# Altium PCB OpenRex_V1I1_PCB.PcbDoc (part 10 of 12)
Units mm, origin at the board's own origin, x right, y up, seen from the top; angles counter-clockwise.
Board outline 70 x 95 mm, 10 copper layers (L1, L2, L3, L4 (PWR), L5 (PWR), L6 (PWR), L7 (PWR), L8, L9, L10), stack 1.632 mm thick; 1080 components, 708 nets, 3831 pads, 2373 vias.
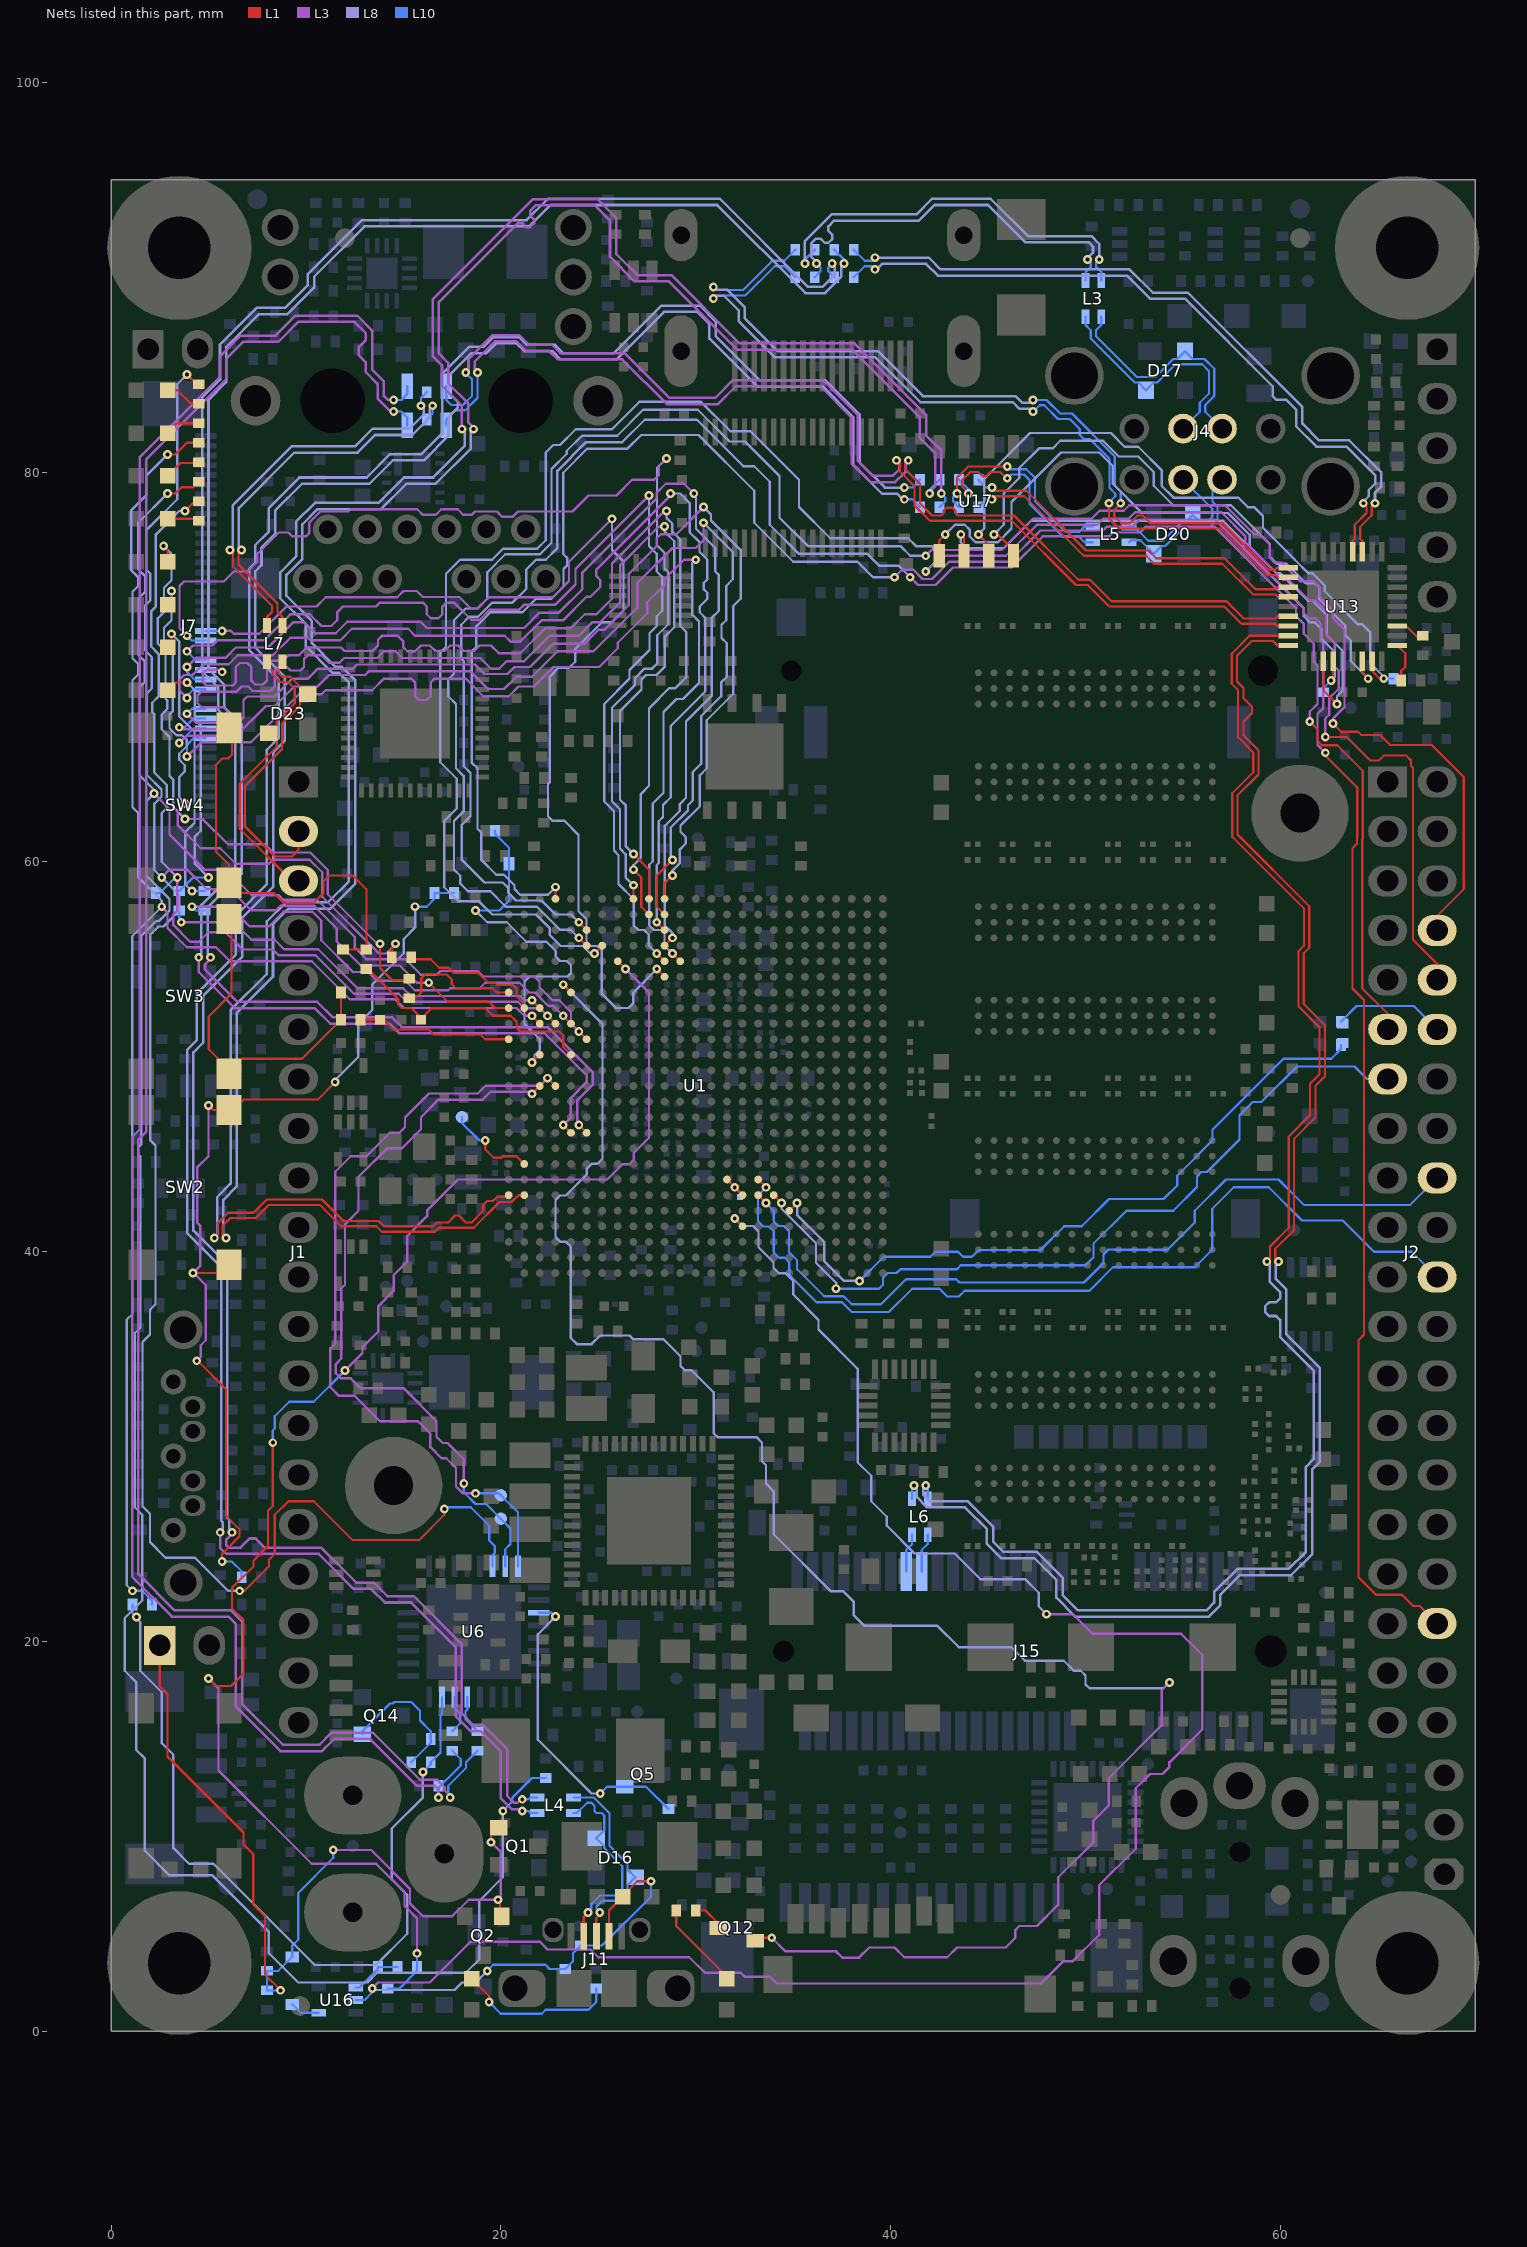
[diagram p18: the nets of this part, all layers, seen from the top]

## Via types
v1: diameter 0.45, hole 0.2, L1 to L10, tented both sides, 2369 vias
v2: diameter 1, hole 0.5, L1 to L10, tented top, 4 vias

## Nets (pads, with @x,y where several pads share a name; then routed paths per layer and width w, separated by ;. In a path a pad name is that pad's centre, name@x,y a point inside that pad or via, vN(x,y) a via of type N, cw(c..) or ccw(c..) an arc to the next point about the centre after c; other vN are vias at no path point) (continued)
UART2_RXD: TP30.1 U1.D13 U6.32 | length 40.9
  L1 w0.114: v1(22.4,48.9) U1.D13@22.8,48.5
  L3 w0.12: v1(18.7,27.6) 18.056,27.6 17.702,27.954 17.702,28.898 17.2,29.4 16.956,29.4 16.385,29.971 16.385,30.659 15.744,31.3 13.8,31.3 12.5,32.6 11.7,32.6 11.255,33.045 11.255,35.047 11.5,35.292 11.5,44.1 12.3,44.9 13.1,44.9 14.3,46.1 14.8,46.1 15.085,46.385 15.085,46.885 16.315,48.115 18.815,48.115 19.215,48.515 22.015,48.515 v1(22.4,48.9)
  L10 w0.114: v1(18.7,27.6) 19.9,27.6 TP30.1@20,27.5 20.875,26.625 U6.32@20.875,23.85
UART2_TXD: TP29.1 U1.C13 U6.31 | length 38
  L1 w0.114: v1(21.6,48.1) U1.C13@22,48.5
  L3 w0.12: v1(18.1,28.1) 18.1,29.344 17.259,30.185 17.015,30.185 16.7,30.5 16.7,31.3 15,33 12.8,33 12.3,33.5 11.8,33.5 11.535,33.765 11.535,34.235 11.815,34.515 11.815,38.115 12,38.3 12,41.4 12.7,42.1 12.7,43.844 14.156,45.3 14.914,45.3 15.9,46.286 15.9,46.9 16.8,47.8 19.068,47.8 19.47,48.202 21.498,48.202 v1(21.6,48.1)
  L10 w0.114: v1(18.1,28.1) 18.1,27.656 18.7,27.056 19.244,27.056 TP29.1@20,26.3 20.5,25.8 20.5,25 20.225,24.725 U6.31@20.225,23.85
UART3_CTS: J2.36 U1.D25 | length 132.1
  L1 w0.114: U1.D25@22.8,58.1 v1(22.8,58.7) ; v1(62.3,65.6) 62.3,65.456 63.94,63.816 63.94,61.282 63.92,61.262 63.92,60.924 63.7,60.704 63.7,53.5 64.285,52.915 64.285,35.745 64,35.46 64,23.3 64.9,22.4 66.23,22.4 66.815,21.815 67.145,21.815 J2.36@68.04,20.92
  L3 w0.12: v1(40.2,74.6) 40.585,74.985 41.171,74.985 41.641,74.515 42.115,74.515 43,75.4 46.083,75.4 47.683,77 50.9,77 51.1,77.2 52.4,77.2 52.767,77.567 56.637,77.567 61.2,73.004 61.2,72.756 61.456,72.5 61.8,72.5 62.056,72.244 62.056,71.344 62.2,71.2 62.2,67.9 61.9,67.6 61.9,66 v1(62.3,65.6)
  L8 w0.12: v1(22.8,58.7) 22.415,58.315 20.985,58.315 20.7,58.6 20.7,58.8 20.16,59.34 19.76,59.34 19,60.1 19,61.5 18.8,61.7 18.8,64.8 18.5,65.1 18.5,70.806 18.735,71.041 18.735,72.079 19.456,72.8 21.1,72.8 21.8,73.5 22.6,73.5 23.218,74.118 23.218,75.018 23.4,75.2 23.4,75.6 23.2,75.8 23.2,79.964 24.436,81.2 26.5,81.2 27.2,81.9 30.144,81.9 33,79.044 33,77.4 35,75.4 38.3,75.4 39.1,74.6 v1(40.2,74.6)
UART3_RTS: J2.11 U1.F23 | length 102.7
  L1 w0.114: v1(24,56.9) U1.F23@24.4,56.5 ; v1(61.5,67.2) 61.9,66.8 61.9,66.2 62.115,65.985 62.915,65.985 64.22,64.68 64.22,61.166 64.2,61.146 64.2,53.5 65.5,52.2 J2.11@65.5,51.4
  L3 w0.12: v1(41,74.6) 41.4,74.2 42.3,74.2 43.2,75.1 46.2,75.1 47.8,76.7 51.2,76.7 51.4,76.9 52.8,76.9 53.1,77.2 56.608,77.2 60.8,73.008 60.8,72.6 61.2,72.2 61.2,71.7 61.71,71.19 61.71,70.28 61.9,70.09 61.9,68.1 61.5,67.7 v1(61.5,67.2)
  L8 w0.12: v1(24,56.9) 23.6,57.3 22.8,57.3 22.08,58.02 20.78,58.02 20.385,58.415 20.385,58.659 20.1,58.944 19.156,58.944 18,60.1 18,61.9 18.445,62.345 18.445,64.555 18.1,64.9 18.1,70.3 17.965,70.435 17.965,72.165 18.37,72.57 18.83,72.57 19.56,73.3 20.6,73.3 21.3,74 21.3,75 21.8,75.5 22.3,75.5 22.9,76.1 22.9,80.06 24.374,81.533 26.233,81.533 27.385,82.685 30.059,82.685 32.444,80.3 33,80.3 33.8,79.5 33.8,77.3 35.3,75.8 38.804,75.8 39.404,75.2 40.4,75.2 v1(41,74.6)
UART3_RXD: J2.10 U1.G22 | length 111.4
  L1 w0.114: v1(24.8,55.3) U1.G22@25.2,55.7 ; v1(62.3,66.4) 63.4,66.4 64.6,65.2 65.044,65.2 65.294,65.45 66.45,65.45 66.7,65.2 66.7,64.926 66.8,64.826 66.8,56 68.04,54.76 J2.10@68.04,53.94
  L3 w0.12: v1(41.8,74.9) 42.6,75.7 45.9,75.7 47.5,77.3 50.6,77.3 50.9,77.6 52.2,77.6 52.533,77.933 56.967,77.933 58.185,76.715 58.185,76.415 60.127,74.473 60.427,74.473 61.5,73.4 61.8,73.4 62.336,72.864 62.336,71.664 62.793,71.207 62.793,70.007 62.985,69.815 62.985,68.885 62.5,68.4 62.5,67.552 62.3,67.352 v1(62.3,66.4)
  L8 w0.12: v1(24.8,55.3) 24.59,55.3 24.205,55.685 23.071,55.685 22.5,56.256 22.5,56.6 21.8,57.3 19.556,57.3 18.885,57.971 18.885,57.985 17.815,57.985 17.1,58.7 17.1,62.1 17.735,62.735 17.735,64.265 16.895,65.105 16.895,70.751 17.185,71.041 17.185,74.785 17.9,75.5 19.551,75.5 20.111,76.06 21.86,76.06 22.3,76.5 22.3,81 22.685,81.385 23.029,81.385 23.844,82.2 25.7,82.2 27.1,83.6 30.267,83.6 31.767,82.1 32.8,82.1 35.3,79.6 35.3,78.2 36.9,76.6 40.9,76.6 41.3,76.2 42.1,76.2 42.3,76 42.3,75.4 v1(41.8,74.9)
UART3_TXD: J2.8 U1.F22 | length 105.7
  L1 w0.114: v1(24,56.1) U1.F22@24.4,55.7 ; v1(62.7,67.1) 63.12,66.68 63.976,66.68 64.141,66.515 65.111,66.515 65.626,66 67.756,66 69.4,64.356 69.4,58.6 68.04,57.24 J2.8@68.04,56.48
  L3 w0.12: v1(41.8,75.7) 42.1,76 45.7,76 47.3,77.6 50.3,77.6 50.715,78.015 51.959,78.015 52.244,78.3 57.155,78.3 58.655,76.8 58.944,76.8 59.456,76.289 59.456,75.6 59.7,75.356 60.044,75.356 61,74.4 61.7,74.4 62,74.1 62,73.6 62.7,72.9 62.7,72.5 63.285,71.915 63.285,67.941 62.7,67.356 v1(62.7,67.1)
  L8 w0.12: v1(24,56.1) 23.585,56.515 23.041,56.515 21.856,57.7 20.256,57.7 19.456,58.5 18.3,58.5 17.915,58.885 17.915,59.285 17.6,59.6 17.6,62.1 18.09,62.59 18.09,64.41 17.7,64.8 17.7,68.1 17.3,68.5 17.3,69.35 17.6,69.65 17.6,72.4 18.2,73 18.8,73 19.3,73.5 19.3,74.853 20.227,75.78 22.007,75.78 22.6,76.373 22.6,80.156 23.385,80.941 23.385,81.089 24.163,81.867 25.967,81.867 27.3,83.2 30.1,83.2 31.732,81.568 32.532,81.568 34.3,79.8 34.3,77.656 35.756,76.2 40.5,76.2 41,75.7 v1(41.8,75.7)
UART4_RXD: J2.13 U1.V6 | length 41.1
  L1 w0.114: U1.V6@34,42.9 v1(34.4,42.5)
  L8 w0.12: v1(34.4,42.5) 34.4,42.2 36.168,40.432 36.168,39.432 37.2,38.4 v1(37.2,38.1)
  L10 w0.114: v1(37.2,38.1) 39.4,38.1 39.6,38.3 39.6,38.644 39.856,38.9 40.3,38.9 40.5,39.1 43.4,39.1 43.6,39.3 50,39.3 50.4,39.7 50.4,40.4 52.1,42.1 54.5,42.1 55.715,43.315 55.715,43.859 55.941,44.085 56.229,44.085 57.9,45.756 57.9,46.994 58.591,47.685 59.029,47.685 60.844,49.5 63.8,49.5 64.44,48.86 J2.13@65.5,48.86
UART4_TXD: R366.1 R367.1 U1.W5 | length 37
  L1 w0.114: U1.W5@34.8,42.1 v1(35.2,42.5)
  L8 w0.12: v1(35.2,42.5) 35.2,41.88 36.6,40.48 36.6,39.5 37.6,38.5 v1(38.4,38.5)
  L10 w0.114: v1(38.4,38.5) 39.64,39.74 42.04,39.74 42.3,40 43.456,40 43.716,39.74 44.17,39.74 44.515,40.085 47.685,40.085 48.9,41.3 49.8,41.3 51.2,42.7 54,42.7 54.7,43.4 54.7,43.9 56.515,45.715 56.515,46.259 60.156,49.9 62.6,49.9 63.1,50.4 R367.1@63.1,50.6
UART4_TXD_R: J2.12 R366.2 R368.2 | length 5.8
  L10 w0.114: R368.2@63.1,51.8 63.9,52.6 66.84,52.6 J2.12@68.04,51.4
UART5_RXD: J2.18 U1.U6 | length 42.9
  L1 w0.114: U1.U6@33.2,42.9 v1(33.6,42.5)
  L10 w0.114: v1(33.6,42.5) 34,42.1 34,41.6 34.015,41.585 34.015,41.541 34.241,41.315 34.529,41.315 34.785,41.059 34.785,39.971 35.2,39.556 35.2,39.1 36.585,37.715 37.585,37.715 38,37.3 39.5,37.3 40.785,38.585 43.359,38.585 43.529,38.415 49.915,38.415 50.915,39.415 50.915,39.859 51.17,40.115 51.459,40.115 51.474,40.1 54.2,40.1 55.6,41.5 55.6,42.1 57.2,43.7 59.9,43.7 61.2,42.4 66.66,42.4 J2.18@68.04,43.78
UART5_TXD: J2.22 U1.U7 | length 46.4
  L1 w0.114: U1.U7@33.2,43.7 v1(33.6,43.3)
  L10 w0.114: v1(33.6,43.3) 33.2,42.9 33.2,41.556 33.471,41.285 33.759,41.285 34,41.044 34,39.956 34.271,39.685 34.559,39.685 34.8,39.444 34.8,38.8 36.2,37.4 37.5,37.4 38,36.9 39.9,36.9 41.1,38.1 42.5,38.1 42.9,37.7 43.5,37.7 43.8,38 50.2,38 51.4,39.2 55.6,39.2 56.5,40.1 56.5,42.2 57.6,43.3 59.4,43.3 61.1,41.6 63.2,41.6 64.8,40 66.74,40 J2.22@68.04,38.7
USB0_CHD: TP26.1 U1.B8 | length 4.7
  L1 w0.114: v1(19.2,45.7) 19.2,45.256 19.641,44.815 20.015,44.815 20.1,44.9 20.8,44.9 U1.B8@21.2,44.5
  L10 w0.114: TP26.1@18,46.9 18,46.6 18.9,45.7 v1(19.2,45.7)
USB0_ID: D19.1 J11.4 R198.1 R199.2 U1.T4 U16.2 | length 119.4
  L1 w0.114: J11.4@25.55,4.875 25.55,6.2 D19.1@26.25,6.9 26.25,6.95 27,7.7 v1(27.7,7.7) ; v1(32,41.7) U1.T4@32.4,41.3
  L3 w0.12: v1(13.4,2.2) 13.7,2.5 16.356,2.5 18.456,4.6 22,4.6 22.4,4.2 24.6,4.2 25,3.8 29.668,3.8 30.468,3 32.305,3 32.5,2.805 33.795,2.805 34.15,2.45 47.71,2.45 48.86,3.6 49.344,3.6 50.7,4.956 50.7,7.5 52.569,9.369 52.569,12.469 53.3,13.2 53.944,13.2 54.3,13.556 54.3,13.796 55.985,15.481 55.985,19.315 54.9,20.4 50.355,20.4 49.355,21.4 v1(48,21.4)
  L8 w0.12: v1(13.4,2.2) 13.485,2.115 17.615,2.115 18,2.5 18.7,2.5 v1(19.3,3.1) ; v1(32,41.7) 32.385,41.315 32.929,41.315 33.215,41.029 33.215,40.229 33.985,39.459 33.985,39.171 34.256,38.9 34.6,38.9 35,38.5 35,37.8 36.3,36.5 36.3,36 38.315,33.985 38.315,29.185 39,28.5 39,27.196 39.8,26.396 39.8,25.944 41.229,24.515 43.285,24.515 44.6,23.2 46.896,23.2 47.6,22.496 47.6,21.8 v1(48,21.4)
  L10 w0.114: U16.2@12.55,1.6 13,1.6 13.4,2 v1(13.4,2.2) ; v1(19.3,3.1) 19.615,3.415 22.285,3.415 22.5,3.2 R199.2@23.3,3.2 23.7,3.6 23.7,4 R198.1@24.1,4.4 25.194,4.4 27.7,6.906 v1(27.7,7.7)
USB0_ID_BUFF: D27.1 U16.4 | length 1.5
  L10 w0.114: D27.1@9.3,1.381 9.731,0.95 U16.4@10.65,0.95
USB0_ID_BUFF_EN: R304.2 R305.2 U1.H21 | length 77.2
  L1 w0.114: v1(5,18.1) 5.385,17.715 6.159,17.715 6.8,18.356 6.8,21.1 6.2,21.7 6.2,22.744 7.315,23.859 7.315,24.159 8.05,24.894 8.05,26.706 8.3,26.956 v1(8.3,30.2) ; U1.H21@26,54.9 v1(26.4,54.5)
  L3 w0.12: v1(5,18.1) 5.515,17.585 5.515,13.385 10.3,8.6 13.6,8.6 15.06,7.14 15.06,6.444 15.7,5.804 v1(15.7,4) ; v1(12,33.9) 12.9,34.8 12.9,35.1 13.715,35.915 13.715,37.215 14.5,38 14.5,38.8 15.195,39.495 15.195,40.805 16.215,41.825 16.215,42.115 17.8,43.7 25.456,43.7 26.241,44.485 26.585,44.485 26.815,44.715 26.815,45.059 27.6,45.844 27.6,53.3 v1(26.4,54.5)
  L10 w0.114: v1(8.3,30.2) 8.3,30.828 8.4,30.928 8.4,31.556 9.144,32.3 10.4,32.3 v1(12,33.9) ; R305.2@14.2,2.2 14.8,2.2 15.7,3.1 R304.2@15.7,3.3 v1(15.7,4)
USB0_ID_BUFF_EN_R: R155.1 R304.1 U16.1 | length 2.6
  L10 w0.114: U16.1@12.55,2.25 12.75,2.25 13.7,3.2 R155.1@13.7,3.3 R304.1@14.7,3.3
USB0_N: R322.2 R323.2 U1.B6 | length 117.6
  L1 w0.114: v1(5.9,40.7) 5.737,40.863 5.737,41.337 6.126,41.726 7.426,41.726 8.1,42.4 10.713,42.4 11.813,41.3 13.613,41.3 13.887,41.026 16.626,41.026 16.826,41.226 18.613,41.226 19.93,42.543 20.548,42.543 20.905,42.9 U1.B6@21.2,42.9
  L3 w0.13: v1(18.6,82.2) 18.6,82.279 18.32,82.559 18.32,83.533 17.3,84.553 17.3,85.604 16.82,86.084 16.82,88.72 20.872,92.772 21.1,92.772 21.304,92.568 21.504,92.568 21.704,92.768 21.704,92.968 21.5,93.172 21.5,93.4 21.78,93.68 24.82,93.68 25.6,92.9 25.6,91.047 26.867,89.78 28.62,89.78 32.12,86.28 38.02,86.28 41.5,82.8 41.5,81.747 42.28,80.967 42.28,79.259 42,78.979 v1(42,78.9)
  L8 w0.13: v1(5.9,40.7) 5.76,40.84 5.76,42.66 6.46,43.36 6.46,52.26 8.31,54.11 8.31,56.81 9.1,57.6 11.253,57.6 12.52,58.867 12.52,69.333 11.833,70.02 11.5,70.02 10.3,71.22 10.3,72.353 9,73.653 9,74.72 9.82,75.54 9.82,77.32 10.6,78.1 13.853,78.1 15.153,79.4 16.653,79.4 18.46,81.207 18.46,82.06 v1(18.6,82.2)
  L10 w0.114: v1(42,78.9) 42,79.1 R323.2@42.5,79.6
USB0_OTG_L_N: D16.2 J11.2 L4.2 | length 10.4
  L1 w0.114: J11.2@24.25,4.875 24.25,5.875 v1(24.475,6.1)
  L10 w0.114: L4.2@23.725,11.2 23.9,11.2 24.426,11.726 24.646,11.726 24.8,11.572 24.8,11.3 24.9,11.2 25.172,11.2 25.3,11.072 25.3,10.3 D16.2@24.9,9.9 25.3,9.5 25.3,9.4 26.226,8.474 26.226,7.313 25.887,6.974 25.099,6.974 24.638,6.513 24.638,6.263 v1(24.475,6.1)
USB0_OTG_L_P: D16.4 J11.3 L4.1 | length 10.5
  L1 w0.114: J11.3@24.9,4.875 24.9,5.797 25.075,5.972 v1(25.075,6.1)
  L10 w0.114: L4.1@23.725,12 24.76,12 25.574,11.186 25.574,9.513 26.5,8.587 26.5,8.3 D16.4@26.9,7.9 26.5,7.5 26.5,7.2 26,6.7 25.212,6.7 24.912,6.4 24.912,6.263 v1(25.075,6.1)
USB0_OTG_N: L4.3 R323.1 | length 128.6
  L3 w0.13: v1(5.6,25.6) 5.6,24.8 5.9,24.5 10.647,24.5 12.447,22.7 13.347,22.7 14.047,22 15.4,22 17.68,19.72 17.68,16.167 18.447,15.4 18.947,15.4 20,14.347 20,11.952 20.552,11.4 21,11.4 v1(21.1,11.3)
  L8 w0.13: v1(5.6,25.6) 5.74,25.74 5.74,26.112 5.646,26.206 5.646,39.205 3.9,40.952 3.9,50.353 4.4,50.853 4.4,53.253 6.4,55.253 6.4,57.253 8,58.853 8,65.753 8.6,66.353 8.6,69.347 7.08,70.867 7.08,75.033 7.4,75.353 7.4,76.253 8.1,76.953 8.1,78.153 9.667,79.72 13.12,79.72 14.32,80.92 15.92,80.92 17,82 17,85.053 18.367,86.42 19.12,86.42 19.62,86.92 20.933,86.92 21.333,86.52 22.78,86.52 23.2,86.1 25.8,86.1 28.235,88.535 30.218,88.535 31.02,87.733 31.02,86.98 33.3,84.7 36.653,84.7 38.41,82.943 38.41,80.49 39.7,79.2 v1(40.7,79.2)
  L10 w0.114: v1(21.1,11.3) 21.41,11.3 21.51,11.2 L4.3@21.875,11.2 ; v1(40.7,79.2) 41.1,79.2 R323.1@41.5,79.6
USB0_OTG_P: L4.4 R326.1 | length 128.6
  L3 w0.13: v1(6.2,25.6) 6.2,25.521 5.92,25.241 5.92,24.933 6.033,24.82 6.645,24.82 7.108,25.283 7.417,25.283 7.88,24.82 10.78,24.82 12.58,23.02 13.48,23.02 14.18,22.32 15.533,22.32 18,19.853 18,16.3 18.58,15.72 19.08,15.72 20.32,14.48 20.32,12.084 20.684,11.72 20.841,11.72 21.021,11.9 v1(21.1,11.9)
  L8 w0.13: v1(6.2,25.6) 6.06,25.74 6.06,26.244 5.966,26.338 5.966,39.338 4.22,41.084 4.22,50.22 4.72,50.72 4.72,53.12 6.72,55.12 6.72,57.12 8.32,58.72 8.32,65.62 8.92,66.22 8.92,69.48 7.4,71 7.4,74.9 7.72,75.22 7.72,76.12 8.42,76.82 8.42,78.02 9.8,79.4 13.253,79.4 14.453,80.6 16.053,80.6 17.32,81.867 17.32,82.82 17.8,83.3 17.8,83.6 17.32,84.08 17.32,84.92 18.5,86.1 19.253,86.1 19.753,86.6 20.8,86.6 21.2,86.2 22.647,86.2 23.067,85.78 25.933,85.78 28.368,88.215 30.085,88.215 30.7,87.6 30.7,86.847 33.167,84.38 36.52,84.38 38.09,82.81 38.09,80.357 39.567,78.88 40.341,78.88 40.621,78.6 v1(40.7,78.6)
  L10 w0.114: v1(21.1,11.9) 21.41,11.9 21.51,12 L4.4@21.875,12 ; v1(40.7,78.6) 41.1,78.6 R326.1@41.5,78.2
USB0_P: R325.2 R326.2 U1.A6 | length 117.6
  L1 w0.114: v1(5.3,40.7) 5.463,40.863 5.463,41.45 6.013,42 7.313,42 7.987,42.674 10.826,42.674 11.926,41.574 13.726,41.574 14,41.3 16.513,41.3 16.713,41.5 17.3,41.5 17.65,41.85 17.85,41.85 18.2,41.5 18.5,41.5 19.1,42.1 19.1,42.4 19.3,42.6 19.6,42.6 19.817,42.817 20.317,42.817 U1.A6@20.4,42.9
  L3 w0.13: v1(18,82.2) 18,83.4 16.98,84.42 16.98,85.472 16.5,85.952 16.5,88.853 21.647,94 24.953,94 25.92,93.033 25.92,91.18 27,90.1 28.753,90.1 32.253,86.6 38.153,86.6 41.82,82.933 41.82,81.88 42.6,81.1 v1(42.6,78.9)
  L8 w0.13: v1(5.3,40.7) 5.44,40.84 5.44,42.793 6.14,43.493 6.14,52.393 7.99,54.243 7.99,56.943 8.967,57.92 11.12,57.92 12.2,59 12.2,69.2 11.7,69.7 11.367,69.7 9.98,71.087 9.98,72.22 8.68,73.52 8.68,74.853 9.5,75.673 9.5,77.453 10.467,78.42 13.72,78.42 15.02,79.72 16.52,79.72 18.14,81.34 18.14,82.06 v1(18,82.2)
  L10 w0.114: R326.2@42.5,78.2 42.8,78.5 42.8,78.7 v1(42.6,78.9)
USB1_HUB_N: R329.1 U13.30 | length 37
  L1 w0.114: U13.30@64.2,75.9 64.2,76.457 64.087,76.57 64.087,77.187 64.687,77.787 64.687,78.237 v1(64.85,78.4)
  L8 w0.13: v1(39.2,91) 41.953,91 42.553,90.4 52.253,90.4 53.453,89.2 55.253,89.2 61.12,83.333 61.12,82.48 61.98,81.62 63.528,81.62 65.177,79.971 65.177,79.267 64.85,78.94 v1(64.85,78.4)
  L10 w0.114: R329.1@38.1,91.4 38.663,90.837 39.037,90.837 v1(39.2,91)
USB1_HUB_P: R332.1 U13.31 | length 37
  L1 w0.114: U13.31@63.7,75.9 63.7,76.457 63.813,76.57 63.813,77.3 64.413,77.9 64.413,78.237 v1(64.25,78.4)
  L8 w0.13: v1(39.2,90.4) 39.279,90.4 39.559,90.68 41.82,90.68 42.42,90.08 52.12,90.08 53.32,88.88 55.12,88.88 59.6,84.4 59.6,83.9 59.8,83.7 60.3,83.7 60.8,83.2 60.8,82.347 61.847,81.3 63.396,81.3 64.857,79.838 64.857,79.4 64.53,79.073 64.53,78.759 64.25,78.479 v1(64.25,78.4)
  L10 w0.114: R332.1@38.1,90 38.663,90.563 39.037,90.563 v1(39.2,90.4)
USB1_N: R328.2 R329.2 U1.F10 | length 98.4
  L1 w0.114: v1(24,46.5) U1.F10@24.4,46.1
  L3 w0.13: v1(5.1,55.1) 5.1,55.021 4.82,54.741 4.82,54.48 6.48,52.82 10.58,52.82 11.38,52.02 14.424,52.02 14.924,51.52 22.384,51.52 24.72,49.184 24.72,48.572 23.91,47.762 23.91,46.59 v1(24,46.5)
  L8 w0.13: v1(5.1,55.1) 4.96,55.24 4.96,57.66 6.7,59.4 6.7,67.053 5.82,67.933 5.82,69.078 5,69.898 5,83.7 5.91,84.61 5.91,86.41 7.6,88.1 9.053,88.1 10.42,89.467 10.42,90.02 13,92.6 21.453,92.6 22.553,93.7 31.1,93.7 35.62,89.18 36.633,89.18 37.46,90.007 37.46,90.56 v1(37.6,90.7)
  L10 w0.114: R329.2@37.1,91.4 37.6,90.9 v1(37.6,90.7)
USB1_P: R331.2 R332.2 U1.E10 | length 98.4
  L1 w0.114: v1(23.2,46.5) U1.E10@23.6,46.1
  L3 w0.13: v1(4.5,55.1) 4.5,54.347 6.347,52.5 10.447,52.5 11.247,51.7 14.292,51.7 14.792,51.2 22.252,51.2 24.4,49.052 24.4,48.704 23.59,47.894 23.59,46.89 v1(23.2,46.5)
  L8 w0.13: v1(4.5,55.1) 4.64,55.24 4.64,57.793 6.38,59.533 6.38,66.92 5.5,67.8 5.5,68.946 4.68,69.766 4.68,83.833 5.59,84.743 5.59,86.543 7.467,88.42 8.92,88.42 10.1,89.6 10.1,90.153 12.867,92.92 21.32,92.92 22.42,94.02 31.233,94.02 35.753,89.5 36.5,89.5 37.14,90.14 37.14,90.56 v1(37,90.7)
  L10 w0.114: v1(37,90.7) 36.8,90.5 36.8,90.3 R332.2@37.1,90
USB_BOT_L_N: D17.2 J4.2 L3.1 | length 12.6
  L10 w0.114: L3.1@50.8,87.975 50.8,87.543 50.537,87.28 50.537,86.963 52.626,84.874 53.574,84.874 54.5,85.8 54.7,85.8 D17.2@55.1,86.2 55.5,85.8 56.1,85.8 56.6,85.3 56.6,83.9 56.137,83.437 56.137,83.093 J4.2@57,82.23
USB_BOT_L_P: D17.4 J4.3 L3.2 | length 12.6
  L10 w0.114: L3.2@50,87.975 50,87.543 50.263,87.28 50.263,86.85 52.513,84.6 52.7,84.6 D17.4@53.1,84.2 53.5,84.6 53.687,84.6 54.613,85.526 55.987,85.526 56.326,85.187 56.326,84.013 55.863,83.551 55.863,83.093 J4.3@55,82.23
USB_BOT_N: L3.4 R327.1 R328.1 | length 21.1
  L8 w0.13: v1(35.6,90.7) 35.6,91.853 36.967,93.22 41.32,93.22 42.12,94.02 45.133,94.02 47.053,92.1 50.3,92.1 50.7,91.7 v1(50.7,90.9)
  L10 w0.114: v1(35.6,90.7) 35.6,90.9 R328.1@36.1,91.4 ; v1(50.7,90.9) 50.537,90.737 50.537,90.52 50.8,90.257 L3.4@50.8,89.825
USB_BOT_P: L3.3 R330.1 R331.1 | length 21.1
  L8 w0.13: v1(36.2,90.7) 36.2,90.779 35.92,91.059 35.92,91.72 36.172,91.972 36.4,91.972 36.607,91.764 36.807,91.764 37.007,91.964 37.007,92.164 36.8,92.372 36.8,92.6 37.1,92.9 41.453,92.9 42.253,93.7 45,93.7 46.92,91.78 50.167,91.78 50.38,91.567 50.38,91.259 50.1,90.979 v1(50.1,90.9)
  L10 w0.114: R331.1@36.1,90 36.4,90.3 36.4,90.5 v1(36.2,90.7) ; L3.3@50,89.825 50,90.257 50.263,90.52 50.263,90.737 v1(50.1,90.9)
USB_CONNECT_OR_USER_LED_2: R388.1 R389.1 U6.15 | length 42.1
  L8 w0.12: v1@1.3,21.2 1.5,21 1.5,18.5 2.6,17.4 2.6,14.785 3.2,14.185 3.2,9.4 4,8.6 5.256,8.6 10.456,3.4 13.6,3.4 15.2,5 15.2,7 14.4,7.8 14.4,10.4 16,12 v1(16,13.3)
  L10 w0.114: R389.1@1.1,21.9 1.1,21.45 v1(1.3,21.25) ; v1@1.275,21.225 v1@1.3,21.2 ; v1(16,13.3) 16.4,13.7 R388.1@16.4,13.8 16.9,14.3 16.9,16.2 16.975,16.275 U6.15@16.975,17.15
USB_CONNECTN: Q14.1 R386.1 R388.2 | length 7.2
  L10 w0.114: Q14.1@12.9,15.25 12.9,15.4 14.315,16.815 14.459,16.815 14.544,16.9 15.4,16.9 15.85,16.45 15.85,15.95 16.4,15.4 R386.1@16.4,15 16.4,14.8 R388.2@15.4,13.8
USB_HDR_L_N: D23.2 J1.2 L7.2 | length 15
  L1 w0.114: L7.2@8.8,70.1 8.594,69.894 8.594,69.694 8.787,69.5 9.2,69.5 D23.2@10.1,68.6 9.7,68.2 9.7,68.013 8.774,67.087 8.774,65.787 6.874,63.887 6.874,61.813 8.407,60.28 9.28,60.28 9.62,60.62 J1.2@9.62,61.56
USB_HDR_L_P: D23.4 J1.3 L7.1 | length 15
  L1 w0.114: L7.1@8,70.275 8,70.1 8.3,69.8 8.3,69.6 8.674,69.226 9.087,69.226 9.426,68.887 9.426,68.126 8.5,67.2 8.5,67 D23.4@8.1,66.6 8.5,66.2 8.5,65.9 6.6,64 6.6,61.7 9.28,59.02 J1.3@9.62,59.02
USB_HDR_N: L7.3 R194.2 R207.1 | length 20.3
  L1 w0.114: v1(6.7,76) 6.537,75.837 6.537,75.25 8.537,73.25 8.537,72.82 8.8,72.557 L7.3@8.8,72.125
  L8 w0.13: v1(6.7,76) 6.56,76.14 6.56,78.16 9.4,81 12.653,81 13.553,81.9 15.453,81.9 16.36,82.807 16.36,83.26 v1(16.5,83.4)
  L10 w0.114: R194.2@16.2,82.7 16.5,83 v1(16.5,83.4)
USB_HDR_P: L7.4 R297.2 R298.1 | length 20.3
  L1 w0.114: v1(6.1,76) 6.263,75.837 6.263,75.137 8.263,73.137 8.263,72.82 8,72.557 L7.4@8,72.125
  L8 w0.13: v1(6.1,76) 6.24,76.14 6.24,78.293 9.267,81.32 12.52,81.32 13.42,82.22 15.32,82.22 16.04,82.94 16.04,83.26 v1(15.9,83.4)
  L10 w0.114: v1(15.9,83.4) 15.9,83.8 R297.2@16.2,84.1
USB_MCU_N: R207.2 R294.2 R299.2 | length 105.6
  L3 w0.13: v1(14.5,83.1) 14.347,83.1 13.68,83.767 13.68,84.52 13.08,85.12 13.08,85.62 12.72,85.98 12.72,86.42 13.08,86.78 13.08,87.12 12.5,87.7 9.6,87.7 8.58,86.68 6.78,86.68 5.9,85.8 5.9,84.747 1.8,80.647 1.8,46.147 1.4,45.747 1.4,23.453 3.253,21.6 6.153,21.6 6.72,21.033 6.72,16.8 8.82,14.7 10.7,14.7 11.32,15.32 13.428,15.32 15.838,12.91 16.733,12.91 17.12,12.523 17.12,12.359 17.4,12.079 v1(17.4,12)
  L10 w0.114: v1(14.5,83.1) 14.9,83.1 15.2,82.8 R207.2@15.2,82.7 R294.2@15.2,82.4 ; v1(17.4,12) 17.3,12.1 17.3,12.6 18.218,13.518 18.218,13.818 R299.2@18.8,14.4
USB_MCU_P: R295.1 R298.2 R300.2 R387.2 | length 105.6
  L3 w0.13: v1(14.5,83.7) 14.2,83.7 14,83.9 14,84.653 13.4,85.253 13.4,87.253 12.633,88.02 9.467,88.02 8.447,87 6.647,87 5.58,85.933 5.58,84.88 1.48,80.78 1.48,46.28 1.08,45.88 1.08,23.32 3.12,21.28 6.02,21.28 6.4,20.9 6.4,16.667 8.687,14.38 10.833,14.38 11.453,15 13.296,15 15.706,12.59 16.6,12.59 16.8,12.39 v1(16.8,12)
  L10 w0.114: v1(14.5,83.7) 14.9,83.7 15.2,84 R298.2@15.2,84.1 R295.1@15.2,84.4 ; v1(16.8,12) 16.8,12.487 16.856,12.544 17.944,13.631 17.944,13.956 R300.2@17.5,14.4
USB_MCU_R_N: R299.1 U6.13 | length 2
  L10 w0.114: U6.13@18.275,17.15 18.275,16.5 18.185,16.41 18.185,16.015 R299.1@18.8,15.4
USB_MCU_R_P: R300.1 U6.14 | length 2
  L10 w0.114: R300.1@17.5,15.4 17.911,15.811 17.911,16.289 17.625,16.575 U6.14@17.625,17.15
USB_MPCIE_L_N: J15.36 L6.1 | length 2
  L10 w0.114: J15.36@41.6,23.6 41.6,24.7 41.9,25 L6.1@41.9,25.475
USB_MPCIE_L_P: J15.38 L6.2 | length 2
  L10 w0.114: J15.38@40.8,23.6 40.8,24.7 41.1,25 L6.2@41.1,25.475
USB_MPCIE_N: L6.4 U13.8 | length 81.6
  L1 w0.114: v1(59.3,39.5) 59.463,39.663 59.463,40.263 60.426,41.226 60.426,45.913 61.52,47.007 61.52,48.62 62.006,49.106 62.006,51.506 60.92,52.593 60.92,55.42 61.2,55.7 61.2,57.613 57.526,61.287 57.526,63.526 58.6,64.6 58.6,65.613 57.826,66.387 57.826,68.803 57.494,69.135 57.494,70.681 58.413,71.6 U13.8@60.4,71.6
  L8 w0.13: v1(41.8,28) 41.66,27.86 41.66,27.54 42,27.2 43.953,27.2 45.26,25.893 45.26,25.14 45.8,24.6 47.5,24.6 48.82,23.28 48.82,22.38 49.6,21.6 56.2,21.6 56.6,22 56.6,22.533 57.787,23.72 60.42,23.72 61.3,24.6 61.3,28.953 61.7,29.353 61.7,33.9 59.98,35.62 59.98,36.5 59.78,36.7 59.413,36.7 59.213,36.9 59.213,37.2 59.413,37.4 59.78,37.4 59.98,37.6 59.98,37.92 59.44,38.46 59.44,39.36 v1(59.3,39.5)
  L10 w0.114: v1(41.8,28) 41.8,27.89 41.9,27.79 L6.4@41.9,27.325
USB_MPCIE_OC: R284.2 U13.21 | length 1.5
  L1 w0.114: U13.21@66,72.1 66.456,72.1 67.056,71.5 67.1,71.5 R284.2@67.3,71.5
USB_MPCIE_P: L6.3 U13.9 | length 81.6
  L1 w0.114: v1(59.9,39.5) 59.737,39.663 59.737,40.15 60.7,41.113 60.7,45.8 61.794,46.894 61.794,48.506 62.28,48.993 62.28,51.62 61.194,52.706 61.194,55.306 61.474,55.587 61.474,57.726 57.8,61.4 57.8,63.413 58.874,64.487 58.874,65.726 58.1,66.5 58.1,67.2 58.54,67.64 58.54,67.96 58.1,68.4 58.1,68.916 57.768,69.248 57.768,70.568 58.526,71.326 59.617,71.326 59.843,71.1 U13.9@60.4,71.1
  L8 w0.13: v1(41.2,28) 41.34,27.86 41.34,27.407 41.867,26.88 43.82,26.88 44.94,25.76 44.94,25.007 45.667,24.28 47.367,24.28 48.5,23.147 48.5,22.247 49.467,21.28 56.333,21.28 56.92,21.867 56.92,22.4 57.92,23.4 60.553,23.4 61.62,24.467 61.62,28.82 62.02,29.22 62.02,34.033 60.3,35.753 60.3,38.053 59.76,38.593 59.76,39.36 v1(59.9,39.5)
  L10 w0.114: L6.3@41.1,27.325 41.1,27.79 41.2,27.89 v1(41.2,28)
USB_OC: R260.1 U1.R7 U1.T6 | length 1.7
  L1 w0.114: U1.R7@31.6,43.7 v1(32,43.3) U1.T6@32.4,42.9
  L10 w0.114: v1(32,43.3) 32.265,43.035 R260.1@32.265,42.8
USB_OTG_EN: D27.2 JP1.1 Q1.1 Q2.1 R174.2 R214.1 | length 45.5
  L1 w0.114: JP1.1@2.5,19.78 2.5,17.7 2.9,17.3 2.9,14.1 6.8,10.2 6.8,9.6 7.3,9.1 7.3,6.5 7.9,5.9 7.9,2.9 v1(8.7,2.1) ; v1(19.5,9.7) 19.5,10.05 Q1.1@19.9,10.45 ; v1(19.85,6.75) 19.95,6.65 Q2.1@19.95,6
  L3 w0.12: v1(11.4,9.3) 13.345,9.3 15.34,7.305 15.34,6.56 16,5.9 17.5,5.9 18.35,6.75 v1(19.85,6.75) 20,6.9 20,9.2 v1(19.5,9.7)
  L10 w0.114: v1(8.7,2.1) R174.2@8,2.1 R214.1@8,3.1 8.581,3.1 D27.2@9.3,3.819 9.3,4.4 9.6,4.7 9.6,7.1 11.4,8.9 v1(11.4,9.3)
USB_TOP_L_N: D20.2 J4.6 L5.2 | length 8
  L10 w0.114: L5.2@52.225,76.4 52.325,76.5 52.8,76.5 D20.2@53.5,75.8 53.9,76.2 54.087,76.2 55.013,77.126 56.326,77.126 56.774,77.574 56.774,78.223 56.515,78.482 56.515,79.125 J4.6@57,79.61
USB_TOP_L_P: D20.4 J4.7 L5.1 | length 8
  L10 w0.114: L5.1@52.225,77.2 52.487,77.2 53.213,76.474 53.974,76.474 54.9,77.4 55.1,77.4 D20.4@55.5,77.8 55.9,77.4 56.213,77.4 56.5,77.687 56.5,78.11 J4.7@55,79.61
USB_TOP_N: L5.3 R321.1 R322.1 | length 11.1
  L1 w0.114: v1(44,78.9) 44,78.925 43.674,79.251 43.674,79.587 44.093,80.006 44.494,80.006 44.7,79.8 44.9,79.8 45.106,80.006 45.629,80.006 45.955,79.68 v1(45.98,79.68)
  L10 w0.114: R322.1@43.5,79.6 44,79.1 v1(44,78.9) ; v1(45.98,79.68) 46.005,79.68 46.195,79.87 46.843,79.87 47.126,79.587 47.126,78.387 48.85,76.663 49.68,76.663 49.943,76.4 L5.3@50.375,76.4
USB_TOP_P: L5.4 R324.1 R325.1 | length 11.1
  L1 w0.114: v1(43.4,78.9) 43.4,79.7 43.98,80.28 v1(45.98,80.28)
  L10 w0.114: v1(43.4,78.9) 43.2,78.7 43.2,78.5 R325.1@43.5,78.2 ; v1(45.98,80.28) 46.116,80.144 46.956,80.144 47.4,79.7 47.4,78.5 48.963,76.937 49.68,76.937 49.943,77.2 L5.4@50.375,77.2
USBDN1_N: R327.2 U13.1 | length 43.5
  L1 w0.114: v1(51.8,78.4) 51.8,78.375 51.474,78.049 51.474,77.726 51.826,77.374 52.274,77.374 52.67,77.77 52.93,77.77 53.326,77.374 57.026,77.374 59.413,74.987 59.73,74.987 59.843,75.1 U13.1@60.4,75.1
  L8 w0.13: v1(30.9,89.5) 31.04,89.36 31.593,89.36 32.52,88.433 32.52,87.88 34.2,86.2 39.353,86.2 41.653,83.9 46.4,83.9 46.74,83.56 47.16,83.56 v1(47.3,83.7)
  L10 w0.114: v1(30.9,89.5) 31.063,89.337 32.437,89.337 33.937,90.837 34.537,90.837 R327.2@35.1,91.4 ; v1(47.3,83.7) 48,83.7 48.7,83 49.3,83 51.5,80.8 51.5,79.3 51.8,79 v1(51.8,78.4)
USBDN1_OC: R285.1 U13.13 U17.2 | length 28.3
  L1 w0.114: v1(43.6,76.8) 43.765,76.635 U17.2@43.765,75.7 ; v1(62.6,69.3) 62.7,69.4 U13.13@62.7,70.3
  L8 w0.12: v1(43.6,76.8) 43.6,76.4 43.9,76.1 45.8,76.1 47.2,77.5 57.056,77.5 58.12,76.436 58.12,76.084 61.2,73.004 61.2,72.6 61.515,72.285 61.759,72.285 62.085,71.959 62.085,71.471 62.8,70.756 62.8,69.5 v1(62.6,69.3)
  L10 w0.114: R285.1@62.2,68.7 62.2,68.9 v1(62.6,69.3)
USBDN1_P: R330.2 U13.2 | length 43.5
  L1 w0.114: v1(51.2,78.4) 51.2,77.613 51.713,77.1 56.913,77.1 59.3,74.713 59.73,74.713 59.843,74.6 U13.2@60.4,74.6
  L8 w0.13: v1(30.9,88.9) 31.04,89.04 31.46,89.04 32.2,88.3 32.2,87.747 34.067,85.88 39.22,85.88 41.52,83.58 46.267,83.58 46.607,83.24 47.16,83.24 v1(47.3,83.1)
  L10 w0.114: v1(30.9,88.9) 31.063,89.063 32.55,89.063 34.05,90.563 34.537,90.563 R330.2@35.1,90 ; v1(47.3,83.1) 47.325,83.1 47.651,83.426 47.887,83.426 48.587,82.726 49.187,82.726 49.7,82.213 49.7,81.9 49.9,81.7 50.213,81.7 51.226,80.687 51.226,79.187 51.526,78.887 51.526,78.751 51.2,78.425 v1(51.2,78.4)
USBDN1_PWR_EN: U13.12 U17.1 | length 36.1
  L1 w0.114: U17.1@42.495,75.7 42.495,76.495 v1@42.795,76.795 ; U13.12@62.2,70.3 62.2,68.8 v1(62.9,68.1)
  L8 w0.12: v1@42.795,76.795 43.3,77.3 43.8,77.3 44.05,77.05 44.05,76.706 44.356,76.4 45.5,76.4 46.2,77.1 46.2,78.46 48.74,81 50.7,81 51.4,80.3 51.4,79.4 52.9,77.9 57.3,77.9 58.415,76.785 58.415,76.191 59.806,74.8 60,74.8 61.4,73.4 61.644,73.4 62.375,72.669 62.375,71.625 63.2,70.8 63.2,68.8 62.9,68.5 v1(62.9,68.1)
  other v1: 42.8,76.8
USBDN2_N: R321.2 U13.3 | length 18.3
  L1 w0.114: v1(45.2,79.2) 45.363,79.037 46.963,79.037 50.026,75.974 53.226,75.974 53.626,75.574 57.126,75.574 58.713,73.987 59.73,73.987 59.843,74.1 U13.3@60.4,74.1
  L10 w0.114: R321.2@44.5,79.6 44.9,79.2 v1(45.2,79.2)
USBDN2_OC: R286.1 U13.17 U17.3 | length 34.7
  L1 w0.114: v1(44.5,76.8) 45.035,76.265 U17.3@45.035,75.7 ; U13.17@64.7,70.3 64.7,69.8 65.1,69.4 v1(65.3,69.4)
  L8 w0.12: v1(44.5,76.8) 44.8,77.1 44.8,79.644 47.156,82 51.3,82 52,81.3 52.7,81.3 53.9,80.1 53.9,79.3 54.512,78.688 57.834,78.688 58.322,78.2 58.644,78.2 59.1,77.744 59.1,77.144 60.73,75.515 60.73,75.5 61.43,74.8 61.655,74.8 62.275,74.18 62.275,73.881 63.971,72.185 64.205,72.185 64.6,71.79 64.6,70.2 65.3,69.5 v1(65.3,69.4)
  L10 w0.114: v1(65.3,69.4) R286.1@65.8,69.4
USBDN2_P: R324.2 U13.4 | length 18.3
  L1 w0.114: v1(45.2,78.6) 45.363,78.763 46.85,78.763 49.913,75.7 53.113,75.7 53.513,75.3 57.013,75.3 58.6,73.713 59.73,73.713 59.843,73.6 U13.4@60.4,73.6
  L10 w0.114: R324.2@44.5,78.2 44.9,78.6 v1(45.2,78.6)
USBDN2_PWR_EN: U13.16 U17.4 | length 32.7
  L1 w0.114: v1(45.3,76.8) 45.5,76.8 46.305,75.995 U17.4@46.305,75.7 ; 64.2,69.744 U13.16@64.2,70.3 64.2,69.7 v1(64.5,69.4)
  L8 w0.12: v1(45.3,76.8) 45.8,77.3 45.8,78.9 46.6,79.7 46.6,80.2 47.615,81.215 48.315,81.215 48.7,81.6 50.9,81.6 51.7,80.8 52.7,80.8 53.5,80 53.5,79.3 54.5,78.3 57.456,78.3 59.465,76.291 59.465,75.635 59.8,75.3 60.3,75.3 61.315,74.285 61.759,74.285 61.985,74.059 61.985,73.47 63.315,72.14 63.315,71.641 63.6,71.356 63.6,70.3 v1(64.5,69.4)
USBDN3_N: R194.1 R294.1 U13.6 | length 57.2
  L1 w0.114: v1(40.9,80.6) 40.737,80.437 40.737,80.15 41.5,79.387 41.5,78.4 42.126,77.774 42.6,77.774 42.726,77.9 42.726,78.015 42.876,78.165 43.176,78.165 43.326,78.015 43.326,77.9 43.452,77.774 46.326,77.774 49.626,74.474 50.226,74.474 51.326,73.374 57.226,73.374 58.113,72.487 59.73,72.487 59.843,72.6 U13.6@60.4,72.6
  L3 w0.13: v1(18.8,85.1) 18.66,85.24 18.66,85.66 19.7,86.7 20.8,86.7 21.28,86.22 22.48,86.22 22.92,85.78 26.22,85.78 28.52,83.48 31.133,83.48 32.053,84.4 36.4,84.4 38,82.8 38,80.447 38.967,79.48 40.233,79.48 40.76,80.007 40.76,80.46 v1(40.9,80.6)
  L10 w0.114: R294.1@17.2,82.4 R194.1@17.2,82.7 17.666,83.166 18.166,83.166 18.8,83.8 v1(18.8,85.1)
USBDN3_OC: R283.2 U13.19 | length 2
  L1 w0.114: U13.19@66,71.1 66.4,70.7 66.4,70 66.2,69.8 R283.2@66.2,69.3
USBDN3_P: R295.2 R297.1 U13.7 | length 57.2
  L1 w0.114: v1(40.3,80.6) 40.463,80.437 40.463,80.037 41.226,79.274 41.226,78.287 42.013,77.5 46.213,77.5 49.513,74.2 50.113,74.2 51.213,73.1 57.113,73.1 58,72.213 59.73,72.213 59.843,72.1 U13.7@60.4,72.1
  L3 w0.13: v1(18.2,85.1) 18.34,85.24 18.34,85.793 19.567,87.02 20.933,87.02 21.413,86.54 22.613,86.54 23.053,86.1 26.353,86.1 28.653,83.8 31,83.8 31.92,84.72 36.533,84.72 38.32,82.933 38.32,80.58 39.1,79.8 40.1,79.8 40.44,80.14 40.44,80.46 v1(40.3,80.6)
  L10 w0.114: R295.2@17.2,84.4 R297.1@17.2,84.1 17.2,83.7 17.46,83.44 18.053,83.44 18.526,83.913 18.526,84.749 18.2,85.075 v1(18.2,85.1)
USER_BTN_1: D35.2 R381.1 U1.C15 | length 20.2
  L1 w0.114: v1(21.6,49.7) U1.C15@22,50.1
  L8 w0.12: v1(18.7,57.5) 19.3,56.9 20.3,56.9 21.3,55.9 22.344,55.9 22.815,55.429 22.815,55.141 23.041,54.915 23.385,54.915 23.6,54.7 23.6,54.3 23.415,54.115 21.471,54.115 21.215,53.859 21.215,51.685 22,50.9 22,50.356 21.725,50.081 21.725,49.825 v1(21.6,49.7)
  L10 w0.114: v1(18.7,57.5) 19.919,57.5 20.419,58 D35.2@20.419,59.9 20.419,60.725 19.7,61.444 R381.1@19.7,61.6
USER_BTN_1_R: R147.1 R149.2 R380.1 SW2.1 SW2.2 | length 49.5
  L1 w0.114: v1(4.2,38.9) 5.525,38.9 SW2.2@6.05,39.425 ; v1(4.4,34.4) 4.444,34.4 5.9,32.944 5.9,26.444 6.585,25.759 6.585,25.385 5.7,24.5 v1(5.7,24.1) ; v1(5,47.5) 5.225,47.275 SW2.1@6.05,47.275 6.275,47.275 6.8,47.8 10.6,47.8 v1(11.5,48.7)
  L3 w0.12: v1(4.4,34.4) 4.6,34.6 4.6,35.2 4.86,35.46 4.86,38.284 4.244,38.9 v1(4.2,38.9) 4.585,39.285 4.585,41.321 4.415,41.491 4.415,44.315 5,44.9 v1(5,47.5)
  L8 w0.12: v1@11.5,48.8 12.685,49.985 12.685,51.685 13.4,52.4 13.4,53.7 15.015,55.315 15.015,56.044 15.6,56.629 v1(15.6,57.7)
  L10 w0.114: v1(5.7,24.1) 6.2,24.1 6.7,23.6 R380.1@6.7,23.3 ; v1(15.6,57.7) 16.2,57.7 16.6,58.1 R147.1@16.6,58.4 R149.2@17.6,58.4
USER_BTN_2: C315.1 R254.1 U1.A16 | length 8
  L1 w0.114: R254.1@12.8,51.9 C315.1@13.8,51.9 14,51.9 14.5,51.4 16.3,51.4 16.565,51.135 18.965,51.135 19.2,50.9 U1.A16@20.4,50.9
USER_BTN_2_R: R251.1 R254.2 SW3.1 SW3.2 | length 17.1
  L1 w0.114: SW3.1@6.05,57.075 6.185,56.94 6.185,53.241 5.015,52.071 5.015,50.385 6.05,49.35 6.05,49.225 6.725,49.9 9.8,49.9 R254.2@11.8,51.9 R251.1@11.8,53.3
USER_BTN_3: C316.1 R255.1 U1.E15 | length 13.6
  L1 w0.114: R255.1@13.1,54.5 13.2,54.5 14.735,52.965 14.735,52.674 14.909,52.5 15.4,52.5 15.9,52 C316.1@15.9,51.944 ; C316.1@15.9,51.9 C316.1@15.9,51.944 ; U1.E15@23.6,50.1 23.2,50.5 23.2,51.1 23,51.3 21,51.3 20.8,51.5 20.8,51.809 20.509,52.1 19.6,52.1 19.215,52.485 16.441,52.485 C316.1@15.9,51.944
USER_BTN_3_R: R252.1 R255.2 SW4.1 SW4.2 | length 21.8
  L1 w0.114: SW4.1@6.05,66.875 6.2,66.725 6.2,65.5 6,65.3 5.7,65.3 5.385,64.985 5.385,60.515 6.05,59.85 SW4.2@6.05,58.925 6.575,58.4 8.344,58.4 8.844,57.9 10.4,57.9 10.9,58.4 10.9,59 11.2,59.3 12.4,59.3 13.1,58.6 R255.2@13.1,55.5 R252.1@11.9,55.5
USER_LED: Q12.1 U1.E19 | length 96.2
  L1 w0.114: v1(23.2,53.7) U1.E19@23.6,53.3 ; Q12.1@33.05,4.65 33.2,4.8 v1(33.9,4.8)
  L3 w0.12: v1(33.9,4.8) 34.6,4.1 37.2,4.1 37.52,3.78 38.38,3.78 38.9,4.3 40.2,4.3 40.7,3.8 42.9,3.8 43.4,4.3 45.9,4.3 46.4,4.8 46.4,5.2 46.6,5.4 47.5,5.4 48.6,6.5 48.6,7.9 50.4,9.7 50.4,10.8 51.185,11.585 51.185,12.985 53.9,15.7 53.9,17.5 v1(54.3,17.9)
  L8 w0.12: v1(23.2,53.7) 25.215,51.685 25.215,44.771 24.959,44.515 24.671,44.515 24.415,44.259 24.415,43.971 23.329,42.885 23.041,42.885 22.8,42.644 22.8,40.756 23.056,40.5 23.344,40.5 23.585,40.259 23.585,35.571 23.9,35.256 24.656,35.256 25.1,35.7 26.6,35.7 26.785,35.515 28.329,35.515 29.215,34.629 29.215,34.141 29.441,33.915 29.785,33.915 30.915,32.785 30.915,30.685 31.115,30.485 33.115,30.485 33.4,30.2 33.4,29.244 33.6,29.044 33.6,28.1 34,27.7 34,25.5 36.915,22.585 37.559,22.585 38.1,22.044 38.1,21.356 38.656,20.8 42.4,20.8 43.5,19.7 46.2,19.7 46.885,19.015 48.885,19.015 49.4,18.5 49.755,18.5 50,18.255 50,17.8 50.2,17.6 54,17.6 v1(54.3,17.9)
USER_LED_1: R145.2 U1.A18 U6.30 | length 111.9
  L1 w0.114: v1(3.9,85) 4.4,84.5 R145.2@4.5,84.5 ; v1(6.6,22.6) 6.844,22.6 8.1,23.856 8.1,24.2 8.4,24.5 8.4,26.5 9.1,27.2 10.4,27.2 12.4,25.2 15.8,25.2 17.1,26.5 v1(17.1,26.8) ; v1(16.3,53.8) 17.273,52.827 19.373,52.827 19.7,52.5 U1.A18@20.4,52.5
  L3 w0.12: v1(2.6,59.2) 3,59.6 3.9,59.6 4.91,58.59 6.11,58.59 7.185,57.515 8.459,57.515 8.694,57.75 10.418,57.75 11.585,56.583 11.585,55.915 12.815,54.685 14.815,54.685 15.7,53.8 v1(16.3,53.8)
  L8 w0.12: 2.015,45.709 2.015,56.259 2.441,56.685 2.685,56.685 3.5,57.5 3.5,58.3 v1(2.6,59.2) 2.22,59.58 2.22,62.976 2.585,63.341 2.585,63.719 1.835,64.469 1.835,68.645 2.09,68.9 2.09,70.51 1.746,70.854 1.746,73.146 2.02,73.42 2.02,74.784 1.8,75.004 1.8,77 3.4,78.6 3.4,84.5 v1(3.9,85) ; 2.02,45.709 2.285,45.444 2.285,37.3 2,37.015 2,35.756 1.615,35.371 1.615,26.941 2,26.556 2,25.1 2.8,24.3 4.3,24.3 6,22.6 v1(6.6,22.6)
  L10 w0.114: v1(17.1,26.8) 17.185,26.885 18.459,26.885 19.4,25.944 19.4,25.185 19.685,24.9 19.685,24.541 19.575,24.431 U6.30@19.575,23.85
USER_LED_2: R165.2 R389.2 U1.C17 | length 86.7
  L1 w0.114: v1(2.9,80.9) 3.3,80.9 3.9,81.5 R165.2@4.5,81.5 ; v1(21.6,52.1) U1.C17@22,51.7
  L3 w0.12: v1(2.6,57.7) 2.9,57.4 2.9,56.6 3.88,55.62 5.38,55.62 6.1,54.9 10.3,54.9 12.245,52.955 14.569,52.955 15.024,52.5 20.8,52.5 21.2,52.1 v1(21.6,52.1)
  L8 w0.12: v1(1.1,22.6) 0.81,22.89 0.81,36.516 1.085,36.791 1.085,56.185 v1(2.6,57.7) 2.6,58 1.385,59.215 1.385,62.515 1.1,62.8 1.1,69.315 1.385,69.6 1.385,70.159 1.1,70.444 1.1,73.856 1.385,74.141 1.385,74.615 1.045,74.955 1.045,78.045 1.8,78.8 1.8,79.8 v1(2.9,80.9)
  L10 w0.114: v1(1.1,22.6) 1.6,22.6 2.1,22.1 R389.2@2.1,21.9
USER_LED_3: R176.2 R391.2 U1.F16 | length 136.9
  L1 w0.114: v1(2.9,78.9) 3.3,78.9 3.615,79.215 4.215,79.215 R176.2@4.5,79.5 ; v1(24,51.3) U1.F16@24.4,50.9
  L3 w0.12: v1(2.2,63.5) 3,62.7 3,61.4 4.8,59.6 5.9,59.6 7.215,58.285 8.615,58.285 8.84,58.06 10.584,58.06 12.5,56.144 12.5,55.6 13.1,55 15.1,55 15.885,54.215 16.715,54.215 16.9,54.4 18.8,54.4 19.085,54.115 21.729,54.115 21.985,53.859 21.985,53.571 22.656,52.9 23,52.9 23.6,52.3 23.6,51.7 v1(24,51.3)
  L8 w0.12: v1(2.9,78.9) 1.4,77.4 1.4,75.008 1.74,74.668 1.74,73.84 1.423,73.523 1.423,70.597 1.737,70.283 1.737,69.237 1.472,68.972 1.472,64.428 2.2,63.7 v1(2.2,63.5) 1.815,63.115 1.815,59.285 3,58.1 3,57.5 2.465,56.965 2.325,56.965 1.55,56.19 1.55,45.494 1.4,45.344 1.4,45 1.515,44.885 1.515,36.115 1.212,35.812 1.212,26.884 1.6,26.497 1.6,22.1 0.7,21.2 0.7,18.5 1.285,17.915 1.285,14.45 1.735,14 1.735,9.261 2.996,8 5.2,8 8.1,5.1 8.1,4 9.6,2.5 13.156,2.5 13.656,3 18.2,3 18.9,3.7 18.9,6.7 20.1,7.9 v1(20.1,11.3)
  L10 w0.114: v1(20.1,11.3) 20.6,11.8 20.6,12 21.6,13 R391.2@22.3,13
USER_LED_4: R189.2 R392.2 U1.D17 | length 47.7
  L1 w0.114: v1(3.8,78) 4.3,78.5 R189.2@4.5,78.5 ; v1(22.4,52.1) U1.D17@22.8,51.7
  L3 w0.12: v1(3.4,59.2) 3.4,57.5 3.2,57.3 3.2,56.756 4.056,55.9 4.5,55.9 4.985,56.385 5.859,56.385 6.744,55.5 8.3,55.5 8.6,55.2 10.5,55.2 12.465,53.235 14.765,53.235 15.17,52.83 20.866,52.83 21.211,52.485 22.015,52.485 v1(22.4,52.1)
  L8 w0.12: v1(3.4,59.2) 2.6,60 2.6,62.5 2.865,62.765 2.865,63.935 2.215,64.585 2.215,67.585 2.115,67.685 2.115,68.159 2.442,68.487 2.442,70.658 2.069,71.031 2.069,72.869 2.3,73.1 2.3,76.8 3.5,78 v1(3.8,78)
  L10 w0.114: R392.2@2.3,58.4 2.5,58.4 3.3,59.2 v1(3.4,59.2)
USER_LED_5: R192.2 U1.A19 | length 6.5
  L1 w0.114: R192.2@15.3,53 15.6,53 15.915,53.315 15.915,54.015 16.115,54.215 17.229,54.215 17.485,53.959 17.485,53.715 17.69,53.51 19.59,53.51 19.8,53.3 U1.A19@20.4,53.3
USER_LED_6: R193.2 U1.B18 | length 7.2
  L1 w0.114: R193.2@15.4,55.1 15.5,55 16.4,55 16.835,54.565 17.335,54.565 17.6,54.3 18.844,54.3 19.354,53.79 19.706,53.79 19.796,53.7 20.6,53.7 20.8,53.5 20.8,53.11 21.2,52.71 U1.B18@21.2,52.5
USER_LED_7: R200.2 U1.E17 | length 24.2
  L1 w0.114: v1(23.2,52.1) U1.E17@23.6,51.7
  L3 w0.12: v1(4.15,57.7) 6.1,57.7 7.1,56.7 8.1,56.7 8.84,57.44 10.332,57.44 10.78,56.992 10.78,55.976 12.411,54.344 13.2,54.344 13.644,53.9 15.1,53.9 15.585,53.415 17.3,53.415 17.4,53.515 18.915,53.515 19.2,53.8 20.956,53.8 21.456,53.3 21.744,53.3 22.434,52.61 22.69,52.61 v1(23.2,52.1)
  L10 w0.114: v1(4.15,57.7) 4.35,57.5 R200.2@4.8,57.5
USER_LED_8: R202.2 U1.C18 | length 20.9
  L1 w0.114: v1(21.6,52.9) U1.C18@22,52.5
  L3 w0.12: v1(3.6,56.9) 6.3,56.9 7.2,56 8.398,56 8.878,55.52 10.636,55.52 12.641,53.515 14.985,53.515 15.385,53.115 20.977,53.115 21.192,52.9 v1(21.6,52.9)
  L10 w0.114: R202.2@3.5,57.5 3.5,57 v1(3.6,56.9)
USER_LED_CPU_D: D21.1 R146.1 | length 4.6
  L1 w0.114: R146.1@29,6.2 29,5.4 31.6,2.8 D21.1@31.6,2.7
USER_LED_CPU_Q: Q12.3 R146.2 | length 1.7
  L1 w0.114: R146.2@30,6.2 30.5,6.2 31.15,5.55 Q12.3@31.15,5.3
USER_LED_D_1: D1.1 R145.1 | length 1.9
  L1 w0.114: D1.1@2.9,84.2 3.4,84.2 4.1,83.5 R145.1@4.5,83.5
USER_LED_D_2: D2.1 R165.1 | length 1.8
  L1 w0.114: D2.1@2.9,82 3.4,82.5 R165.1@4.5,82.5
USER_LED_D_3: D3.1 R176.1 | length 1.9
  L1 w0.114: D3.1@2.9,79.8 3.565,80.465 R176.1@4.5,80.465
USER_LED_D_4: D33.1 R189.1 | length 1.6
  L1 w0.114: D33.1@2.9,77.6 4.4,77.6 R189.1@4.5,77.5
USER_LED_D_5: D5.1 R192.1 | length 32.6
  L1 w0.114: v1(2.7,76.2) 2.9,76 D5.1@2.9,75.4 ; v1(13.8,55.8) 13.8,54.556 14.441,53.915 15.215,53.915 R192.1@15.3,54
  L3 w0.12: v1(3.8,62.2) 4.7,62.2 6,60.9 7.9,60.9 8.32,60.48 10.216,60.48 11.115,59.581 11.115,58.341 13.656,55.8 v1(13.8,55.8)
  L8 w0.12: v1(2.7,76.2) 3.1,75.8 3.1,74.444 2.715,74.059 2.715,72.815 2.392,72.492 2.392,71.208 2.795,70.805 2.795,68.372 2.885,68.282 2.885,67.841 2.6,67.556 2.6,66.804 3,66.404 3,64.4 3.2,64.2 3.2,62.8 v1(3.8,62.2)
USER_LED_D_6: D6.1 R193.1 | length 30.3
  L1 w0.114: D6.1@2.9,73.2 3.1,73.4 v1(3.1,73.9) ; R193.1@14.4,55.1 14.4,55.6 v1(14.6,55.8)
  L3 w0.12: v1(3.8,63) 3.415,62.615 3.415,61.885 4.6,60.7 5.6,60.7 6.4,59.9 8.1,59.9 8.3,60.1 10.2,60.1 10.835,59.465 10.835,58.205 13.74,55.3 14.123,55.3 v1@14.623,55.8
  L8 w0.12: v1(3.1,73.9) 3.1,72.4 2.715,72.015 2.715,71.385 3.165,70.935 3.165,67.725 3,67.56 3,66.856 3.356,66.5 3.644,66.5 3.885,66.259 3.885,65.929 3.5,65.544 3.5,65.244 3.785,64.959 3.785,64.641 3.5,64.356 3.5,63.3 v1(3.8,63)
USER_LED_D_7: D7.1 R200.1 | length 15.5
  L1 w0.114: D7.1@2.9,71 3.1,71.2 v1(3.1,71.7)
  L8 w0.12: v1(3.1,71.7) 3.5,71.3 3.5,67.456 4.285,66.671 4.285,62 3.8,61.515 3.8,58.85 v1(4.15,58.5)
  L10 w0.114: v1(4.15,58.5) R200.1@4.8,58.5
USER_LED_D_8: D34.1 R202.1 | length 13.7
  L1 w0.114: D34.1@2.9,68.8 3.3,69.2 v1(3.9,69.2)
  L8 w0.12: v1(3.9,69.2) 4.3,68.8 4.3,67.3 4.6,67 4.6,61.6 4.3,61.3 4.3,59.9 v1(5,59.2)
  L10 w0.114: R202.1@3.5,58.5 4.2,59.2 v1(5,59.2)
USER_LED_MCU: Q5.1 R204.1 U6.3 | length 16.1
  L8 w0.12: v1(22.8,21.275) 21.9,20.375 21.9,14.956 24.656,12.2 v1(25.1,12.2)
  L10 w0.114: U6.3@21.95,21.475 22.6,21.475 v1(22.8,21.275) ; v1(25.1,12.2) 25.45,12.55 Q5.1@26.35,12.55 27.45,12.55 R204.1@28.6,11.4
USER_LED_MCU_D: D24.1 R186.1 | length 8.3
  L1 w0.114: D24.1@18.5,2.7 19.4,1.8 v1(19.4,1.5)
  L10 w0.114: v1(19.4,1.5) 20,0.9 22.1,0.9 22.3,1.1 24.5,1.1 24.9,1.5 R186.1@24.9,2.2
VID_IN_CSI1_D0: J7.9 U1.M21 | length 58.1
  L1 w0.114: v1(28.8,55.3) U1.M21@29.2,54.9
  L3 w0.12: v1(3.9,65.4) 4.635,66.135 7.179,66.135 9.644,68.6 10.8,68.6 11,68.8 13.4,68.8 14,69.4 15.4,69.4 15.6,69.2 15.6,68.5 15.8,68.3 16.2,68.3 16.4,68.5 16.4,69.2 16.6,69.4 18.2,69.4 19.1,68.5 20.4,68.5 20.9,69 21.7,69 22.7,70 25.044,70 26,70.956 26,71.244 27.515,72.759 27.515,73.315 28.4,74.2 28.4,74.5 29.4,75.5 v1(30,75.5)
  L8 w0.12: v1(28.8,55.3) 28.4,55.7 28.4,56.345 28.245,56.5 27.856,56.5 27.615,56.741 27.615,59.847 27.797,60.029 27.797,62.997 28.343,63.543 28.343,67.688 29.011,68.355 29.347,68.355 30.163,69.171 30.163,72.337 29.815,72.685 29.815,75.315 v1(30,75.5)
  L10 w0.114: v1(3.9,65.4) 3.9,66 4.25,66.35 J7.9@4.85,66.35
VID_IN_CSI1_D1: J7.10 U1.L24 | length 58.1
  L1 w0.114: U1.L24@28.4,57.3 28,57.7 28,59.3 v1(28.8,60.1)
  L3 w0.12: v1(3.5,66.1) 3.868,66.468 6.413,66.468 7.944,68 8.4,68 9.4,69 10.6,69 11.185,69.585 13.041,69.585 13.241,69.785 18.415,69.785 19.335,68.865 20.165,68.865 20.8,69.5 21.6,69.5 22.9,70.8 24.756,70.8 27,73.044 27,74.3 28.8,76.1 30,76.1 30.4,76.5 v1(30.4,77.4)
  L8 w0.12: v1(28.8,60.1) 28.715,60.185 28.715,61.755 29.6,62.64 29.6,62.9 29.85,63.15 29.85,64.606 30.285,65.041 30.285,67.485 31.3,68.5 31.3,69.2 31.585,69.485 31.585,71.215 31.32,71.48 31.32,72.16 31.56,72.4 31.56,74.156 31.9,74.496 31.9,75.9 v1(30.4,77.4)
  L10 w0.114: v1(3.5,66.1) 4.25,66.85 J7.10@4.85,66.85
VID_IN_CSI1_D2: J7.11 U1.L25 | length 58
  L1 w0.114: U1.L25@28.4,58.1 28.4,58.9 v1(28.8,59.3)
  L3 w0.12: v1(3.5,66.9) 3.598,66.802 6.202,66.802 6.8,67.4 6.8,68.3 6.985,68.485 8.385,68.485 9.3,69.4 10.1,69.4 10.6,69.9 12.4,69.9 12.623,70.123 18.677,70.123 19.165,69.635 20.335,69.635 20.7,70 21.5,70 22.697,71.197 24.297,71.197 25,71.9 25.3,71.9 26.567,73.167 26.567,74.767 28,76.2 28,76.6 28.2,76.8 29,76.8 v1(30.4,78.2)
  L8 w0.12: v1(28.8,59.3) 28.8,59.556 29.185,59.941 29.185,60.641 29.485,60.941 29.485,61.271 29.215,61.541 29.215,61.859 30.2,62.844 30.2,64.435 30.565,64.8 30.565,67.265 31.92,68.62 31.92,73.12 32.3,73.5 32.3,76.004 30.785,77.519 30.785,77.815 v1(30.4,78.2)
  L10 w0.114: v1(3.5,66.9) 3.785,66.9 4.235,67.35 J7.11@4.85,67.35
VID_IN_CSI1_D3: J7.12 U1.K25 | length 58.1
  L1 w0.114: v1(26.8,60.4) 27.6,59.6 U1.K25@27.6,58.1
  L3 w0.12: v1(3.9,67.6) 4.365,67.135 5.765,67.135 5.965,67.335 5.965,67.735 5.765,67.935 4.635,67.935 4.435,68.135 4.435,68.535 4.635,68.735 6.435,68.735 6.7,69 7.035,69 7.27,68.765 8.165,68.765 8.4,69 8.4,69.8 8.6,70 9.015,70 9.2,69.815 9.715,69.815 9.9,70 9.9,70.4 10.1,70.6 10.8,70.6 11.185,70.215 11.341,70.215 11.715,70.215 11.962,70.462 13.662,70.462 14,70.8 14.6,70.8 14.938,70.462 18.938,70.462 19.485,69.915 19.915,69.915 20.3,70.3 21.2,70.3 22.494,71.594 23.994,71.594 24.7,72.3 25.1,72.3 26.133,73.333 26.133,75.237 28.096,77.2 v1(28.4,77.2)
  L8 w0.12: v1(26.8,60.4) 26.415,60.785 26.415,62.885 26.109,63.191 26.109,67.744 27.215,68.85 27.215,69.359 27.441,69.585 27.985,69.585 28.415,70.015 28.415,71.559 28.897,72.041 28.897,76.447 28.4,76.944 v1(28.4,77.2)
  L10 w0.114: v1(3.9,67.6) 4.15,67.85 J7.12@4.85,67.85
VID_IN_CSI1_D4: J7.14 U1.L23 | length 58.1
  L1 w0.114: v1(28,56.9) U1.L23@28.4,56.5
  L3 w0.12: v1(3.9,68.4) 3.515,68.785 3.515,69.359 3.741,69.585 4.185,69.585 4.735,70.135 6.035,70.135 6.5,70.6 8.3,70.6 9.2,71.5 10.1,71.5 10.233,71.367 11.767,71.367 12.355,71.955 15.245,71.955 15.6,71.6 20.2,71.6 20.5,71.3 21,71.3 22.089,72.389 23.183,72.389 24.394,73.6 24.6,73.6 25.1,74.1 25.1,74.464 24.9,74.664 24.9,75 28.7,78.8 v1(28.7,78.9)
  L8 w0.12: v1(28,56.9) 28,59.836 28.103,59.939 28.103,62.087 28.322,62.306 28.322,62.922 28.715,63.315 28.715,66.971 30.489,68.745 30.489,72.517 30.2,72.806 30.2,73.1 30.585,73.485 30.585,73.809 30.415,73.979 30.415,74.321 30.585,74.491 30.585,75.515 30.192,75.908 30.192,76.408 29.685,76.915 29.685,78.415 29.2,78.9 v1(28.7,78.9)
  L10 w0.114: v1(3.9,68.4) 3.9,68.5 4.25,68.85 J7.14@4.85,68.85
VID_IN_CSI1_D5: J7.15 U1.L22 | length 58.1
  L1 w0.114: U1.L22@28.4,55.7 v1(28.8,56.1)
  L3 w0.12: v1(3.9,70) 4.365,70.465 5.865,70.465 6.4,71 8.056,71 9.356,72.3 9.9,72.3 10.467,71.733 11.533,71.733 12.115,72.315 15.88,72.315 16.195,72 21.2,72 21.986,72.786 22.986,72.786 24.182,73.982 24.182,74.838 27.985,78.641 27.985,78.93 28.456,79.4 29.4,79.4 v1(29.9,78.9)
  L8 w0.12: v1(28.8,56.1) 28.8,56.356 28.409,56.747 28.409,61.845 29.185,62.621 29.185,62.971 29.5,63.286 29.5,67.2 30.815,68.515 30.815,72.515 31.185,72.885 31.185,74.715 31,74.9 31,76.1 30.015,77.085 30.015,78.785 v1(29.9,78.9)
  L10 w0.114: v1(3.9,70) 3.9,69.744 4.294,69.35 J7.15@4.85,69.35
VID_IN_CSI1_D6: J7.16 U1.K24 | length 58
  L1 w0.114: v1(26.8,59.6) 27.2,59.2 27.2,57.7 U1.K24@27.6,57.3
  L3 w0.12: v1(5.7,69.75) 5.6,69.85 4.9,69.85 4.7,69.65 4.7,69.25 4.9,69.05 6.25,69.05 6.4,69.2 6.4,70 6.6,70.2 7,70.2 7.2,70 7.2,69.3 7.4,69.1 7.8,69.1 8,69.3 8,70.1 8.22,70.32 8.82,70.32 9.1,70.6 9.644,70.6 10.044,71 11.8,71 11.985,70.815 13.421,70.815 13.7,71.094 13.7,71.4 13.894,71.594 14.706,71.594 15,71.3 15,71 15.2,70.8 15.6,70.8 15.9,71.1 16.356,71.1 16.641,70.815 17.115,70.815 17.4,71.1 17.8,71.1 18.085,70.815 18.615,70.815 18.9,71.1 19.5,71.1 19.9,70.7 21,70.7 22.291,71.991 23.591,71.991 24.3,72.7 24.9,72.7 25.7,73.5 25.7,75.3 28.4,78 v1(28.5,78)
  L8 w0.12: v1(26.8,59.6) 26.8,59.824 27.185,60.209 27.185,63.485 27.6,63.9 27.6,67.874 28.641,68.915 28.959,68.915 29.511,69.467 29.511,71.789 29.203,72.097 29.203,76.537 28.8,76.94 28.8,77.344 28.5,77.644 v1(28.5,78)
  L10 w0.114: J7.16@4.85,69.85 5.6,69.85 v1(5.7,69.75)
VID_IN_CSI1_D7: J7.17 U1.L21 | length 58.1
  L1 w0.114: v1(28,55.3) U1.L21@28.4,54.9
  L3 w0.12: v1(3.9,70.8) 4.2,71.1 5.2,71.1 5.475,71.375 7.875,71.375 9.2,72.7 10.2,72.7 10.8,72.1 11.3,72.1 11.6,72.4 11.6,72.8 11.9,73.1 13.6,73.1 13.8,73.3 16,73.3 16.2,73.1 16.2,72.7 16.4,72.5 16.8,72.5 17,72.7 17,73.1 17.2,73.3 17.6,73.3 18.48,72.42 18.92,72.42 19.44,72.94 20.94,72.94 21.183,73.183 22.783,73.183 23.832,74.233 23.832,75.032 v1(27.6,78.8)
  L8 w0.12: v1(27.6,78.8) 27.6,76.2 28,75.8 28,74.904 28.285,74.619 28.285,72.885 28,72.6 28,72.1 27.627,71.727 27.627,70.871 26.6,69.844 26.6,69.4 25.302,68.102 25.302,63.098 25.805,62.595 25.805,60.575 26.04,60.34 26.04,58.86 26.815,58.085 26.815,56.741 27.056,56.5 27.344,56.5 27.585,56.259 27.585,55.715 v1(28,55.3)
  L10 w0.114: v1(3.9,70.8) 4.35,70.35 J7.17@4.85,70.35
VID_IN_CSI1_D8: J7.19 U1.J25 | length 58.1
  L1 w0.114: U1.J25@26.8,58.1 v1(26.8,58.8)
  L3 w0.12: v1(3.9,71.6) 3.515,71.985 3.515,74.159 3.741,74.385 5.785,74.385 6.3,74.9 7,74.9 7.5,75.4 7.5,75.8 8.6,76.9 9.1,76.9 9.3,76.7 10,76.7 10.163,76.863 10.163,77.4 10.738,77.975 12.175,77.975 12.287,78.087 15.712,78.087 16,77.8 16.659,77.8 16.947,78.087 17.787,78.087 18.075,77.8 18.5,77.8 18.675,77.975 19.8,77.975 20.075,77.7 20.6,77.7 20.875,77.975 23.675,77.975 24.5,78.8 25.932,78.8 26.732,79.6 27.864,79.6 28.1,79.836 28.1,80.3 v1(28.5,80.7)
  L8 w0.12: v1(26.8,58.8) 26.4,59.2 26.4,60.39 26.11,60.68 26.11,62.703 25.705,63.107 25.705,67.905 26.88,69.08 26.88,69.42 27.375,69.915 27.759,69.915 28.021,70.176 28.021,71.621 28.591,72.191 28.591,74.859 28.4,75.05 28.4,75.856 28.015,76.241 28.015,80.215 v1(28.5,80.7)
  L10 w0.114: v1(3.9,71.6) 4.15,71.35 J7.19@4.85,71.35
VID_IN_CSI1_D9: J7.20 U1.L20 | length 58.1
  L1 w0.114: v1(28,54.5) U1.L20@28.4,54.1
  L3 w0.12: v1(5.7,71.85) 6.15,71.85 6.3,71.7 7.6,71.7 9,73.1 10.54,73.1 11.02,73.58 14.68,73.58 15,73.9 15.68,73.9 15.989,73.591 17.865,73.591 18.456,73 18.8,73 19.38,73.58 22.667,73.58 23.5,74.413 23.5,75.4 v1(25.7,77.6)
  L8 w0.12: v1(25.7,77.6) 25.7,76 26.295,75.405 26.295,72.895 25.7,72.3 25.2,72.3 23.815,70.915 23.815,70.271 23.5,69.956 22.956,69.956 22.515,69.515 22.515,64.1 22.415,64 22.415,62.659 22.415,62.341 22.641,62.115 23.255,62.115 23.985,61.385 23.985,57.468 24.395,57.058 24.395,55.905 24.615,55.685 24.959,55.685 25.185,55.459 25.185,53.215 25.9,52.5 26.544,52.5 26.8,52.756 26.8,53.3 v1(28,54.5)
  L10 w0.114: J7.20@4.85,71.85 v1(5.7,71.85)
